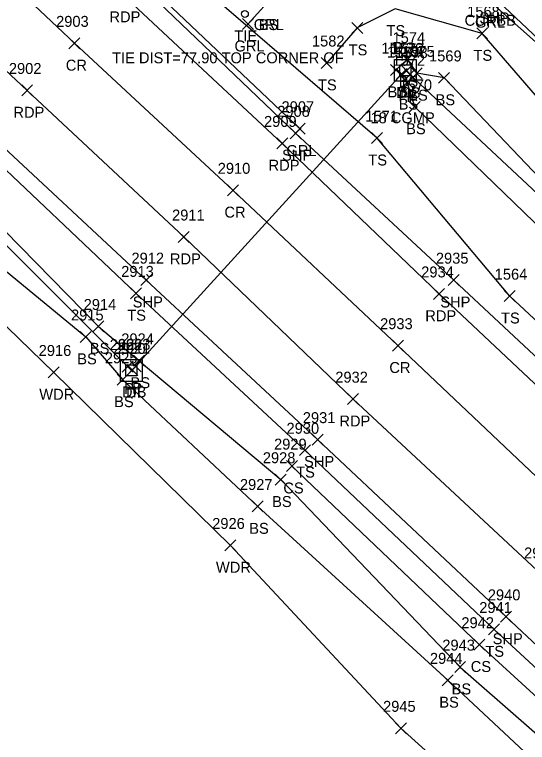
# Model space of a CAD drawing. Extents: x 1647574 to 1652703, y 212895 to 228670.
# Drawn here: x 1649146.1 to 1649239.7, y 226821.7 to 226954.6 of the extents above; entities that cross this region are included whole.
import ezdxf

# ---------------------------------------------------------------- set-up
doc = ezdxf.new("R2010")
doc.units = 0
for name, color, linetype in [('C_A', 7, 'Continuous'), ('C_C', 7, 'Continuous'), ('CBP', 7, 'Continuous'), ('D_A', 7, 'Continuous'), ('D_C', 7, 'Continuous'), ('D_I', 7, 'Continuous'), ('D_TIC', 7, 'Continuous'), ('DCP', 7, 'Continuous'), ('DS', 7, 'Continuous'), ('L_A', 7, 'Continuous'), ('L_I', 7, 'Continuous'), ('L_TIC', 7, 'Continuous'), ('LAWA', 7, 'Continuous'), ('LELB', 7, 'Continuous'), ('P_A', 7, 'Continuous'), ('P_I', 7, 'Continuous'), ('P_TIC', 7, 'Continuous'), ('PET', 7, 'Continuous'), ('PRC', 7, 'Continuous'), ('PSP', 7, 'Continuous'), ('R_A', 7, 'Continuous'), ('R_I', 7, 'Continuous'), ('R_TIC', 7, 'Continuous'), ('RGR', 7, 'Continuous')]:
    doc.layers.add(name, color=color, linetype=linetype)

msp = doc.modelspace()

# ---------------------------------------------------------------- linework, layer by layer
at = {"layer": 'CBP'}
msp.add_circle((1649188.13, 226954.68), 0.625, dxfattribs=at)
at = {"layer": 'D_TIC'}
for points in [[(1649215.77, 226942.73), (1649217.77, 226944.73)], [(1649217.77, 226942.73), (1649215.77, 226944.73)], [(1649216.65, 226943.32), (1649218.65, 226945.32)], [(1649218.65, 226943.32), (1649216.65, 226945.32)], [(1649217.25, 226942.62), (1649219.25, 226944.62)], [(1649219.25, 226942.62), (1649217.25, 226944.62)], [(1649165.73, 226889.31), (1649167.73, 226891.31)], [(1649167.73, 226889.31), (1649165.73, 226891.31)], [(1649166.59, 226888.68), (1649168.59, 226890.68)], [(1649168.59, 226888.68), (1649166.59, 226890.68)], [(1649167.19, 226889.36), (1649169.19, 226891.36)], [(1649169.19, 226889.36), (1649167.19, 226891.36)]]:
    msp.add_lwpolyline(points, dxfattribs=at)
at = {"layer": 'DCP'}
for points in [[(1649216.77, 226943.73), (1649168.19, 226890.36)], [(1649314.43, 226853.77), (1649218.25, 226943.62)], [(1649132.42, 226924.52), (1649166.73, 226890.31)]]:
    msp.add_lwpolyline(points, dxfattribs=at)
at = {"layer": 'DS'}
for p, q in [((1649215.43, 226946.39), (1649219.43, 226946.39)), ((1649215.43, 226942.39), (1649215.43, 226946.39)), ((1649219.43, 226946.39), (1649219.43, 226942.39)), ((1649216.43, 226943.39), (1649216.43, 226945.39)), ((1649216.43, 226945.39), (1649218.43, 226945.39)), ((1649218.43, 226945.39), (1649218.43, 226943.39)), ((1649218.43, 226943.39), (1649216.43, 226943.39)), ((1649217.44, 226944.39), (1649217.44, 226944.39)), ((1649217.44, 226944.39), (1649217.44, 226944.39)), ((1649219.43, 226942.39), (1649215.43, 226942.39)), ((1649165.41, 226891.6), (1649169.41, 226891.6)), ((1649165.41, 226887.6), (1649165.41, 226891.6)), ((1649169.41, 226891.6), (1649169.41, 226887.6)), ((1649166.41, 226888.6), (1649166.41, 226890.6)), ((1649166.41, 226890.6), (1649168.41, 226890.6)), ((1649168.41, 226890.6), (1649168.41, 226888.6)), ((1649167.42, 226889.6), (1649167.42, 226889.6)), ((1649167.42, 226889.6), (1649167.42, 226889.6)), ((1649169.41, 226887.6), (1649165.41, 226887.6)), ((1649168.41, 226888.6), (1649166.41, 226888.6))]:
    msp.add_line(p, q, dxfattribs=at)
at = {"layer": 'L_TIC'}
for points in [[(1649207.66, 226951.13), (1649209.66, 226953.13)], [(1649209.66, 226951.13), (1649207.66, 226953.13)], [(1649230.46, 226950.13), (1649232.46, 226952.13)], [(1649232.46, 226950.13), (1649230.46, 226952.13)], [(1649216.78, 226945.35), (1649218.78, 226947.35)], [(1649218.78, 226945.35), (1649216.78, 226947.35)], [(1649202.07, 226944.74), (1649204.07, 226946.74)], [(1649204.07, 226944.74), (1649202.07, 226946.74)], [(1649214.75, 226943.46), (1649216.75, 226945.46)], [(1649216.75, 226943.46), (1649214.75, 226945.46)], [(1649218.53, 226942.85), (1649220.53, 226944.85)], [(1649220.53, 226942.85), (1649218.53, 226944.85)], [(1649218.53, 226942.85), (1649220.53, 226944.85)], [(1649220.53, 226942.85), (1649218.53, 226944.85)], [(1649223.51, 226942.02), (1649225.51, 226944.02)], [(1649225.51, 226942.02), (1649223.51, 226944.02)], [(1649216.77, 226941.22), (1649218.77, 226943.22)], [(1649218.77, 226941.22), (1649216.77, 226943.22)], [(1649218.14, 226936.73), (1649220.14, 226938.73)], [(1649220.14, 226936.73), (1649218.14, 226938.73)], [(1649211.26, 226931.02), (1649213.26, 226933.02)], [(1649213.26, 226931.02), (1649211.26, 226933.02)], [(1649167.25, 226902.68), (1649169.25, 226904.68)], [(1649169.25, 226902.68), (1649167.25, 226904.68)], [(1649235.49, 226902.17), (1649237.49, 226904.17)], [(1649237.49, 226902.17), (1649235.49, 226904.17)], [(1649160.39, 226896.64), (1649162.39, 226898.64)], [(1649162.39, 226896.64), (1649160.39, 226898.64)], [(1649158.08, 226894.72), (1649160.08, 226896.72)], [(1649160.08, 226894.72), (1649158.08, 226896.72)], [(1649167.83, 226890.36), (1649169.83, 226892.36)], [(1649169.83, 226890.36), (1649167.83, 226892.36)], [(1649152.24, 226888.24), (1649154.24, 226890.24)], [(1649154.24, 226888.24), (1649152.24, 226890.24)], [(1649164.83, 226886.9), (1649166.83, 226888.9)], [(1649166.83, 226886.9), (1649164.83, 226888.9)], [(1649198.09, 226874.04), (1649200.09, 226876.04)], [(1649200.09, 226874.04), (1649198.09, 226876.04)], [(1649195.72, 226871.14), (1649197.72, 226873.14)], [(1649197.72, 226871.14), (1649195.72, 226873.14)], [(1649193.67, 226868.66), (1649195.67, 226870.66)], [(1649195.67, 226868.66), (1649193.67, 226870.66)], [(1649189.49, 226863.77), (1649191.49, 226865.77)], [(1649191.49, 226863.77), (1649189.49, 226865.77)], [(1649184.49, 226856.66), (1649186.49, 226858.66)], [(1649186.49, 226856.66), (1649184.49, 226858.66)], [(1649232.63, 226841.31), (1649234.63, 226843.31)], [(1649234.63, 226841.31), (1649232.63, 226843.31)], [(1649229.92, 226838.54), (1649231.92, 226840.54)], [(1649231.92, 226838.54), (1649229.92, 226840.54)], [(1649226.44, 226834.45), (1649228.44, 226836.45)], [(1649228.44, 226834.45), (1649226.44, 226836.45)], [(1649224.18, 226832.03), (1649226.18, 226834.03)], [(1649226.18, 226832.03), (1649224.18, 226834.03)], [(1649215.62, 226823.27), (1649217.62, 226825.27)], [(1649217.62, 226823.27), (1649215.62, 226825.27)]]:
    msp.add_lwpolyline(points, dxfattribs=at)
at = {"layer": 'LAWA'}
msp.add_lwpolyline([(1649041.49, 226996.32), (1649066.6, 226982.43), (1649084.99, 226955.58), (1649104.57, 226936.43), (1649153.24, 226889.24), (1649185.49, 226857.66), (1649216.62, 226824.27), (1649251.65, 226792.59), (1649287.92, 226760.12), (1649326.63, 226723.53), (1649357.26, 226688), (1649386.17, 226657.62), (1649416.75, 226628.4), (1649449.74, 226597.57), (1649490.53, 226561.68), (1649523.77, 226531.6), (1649564.01, 226501.21), (1649600.78, 226471.1)], dxfattribs=at)
at = {"layer": 'LELB'}
for points in [[(1649050.36, 227022.26), (1649054.5, 227019.16), (1649077.5, 226992.81), (1649097.35, 226965.43), (1649118.34, 226949.96), (1649138.54, 226931.84), (1649168.25, 226903.68), (1649199.09, 226875.04), (1649233.63, 226842.31), (1649267.99, 226810.62), (1649300.85, 226778.49), (1649342.51, 226739.65), (1649376.73, 226707.3), (1649405.44, 226679.92), (1649436.03, 226650.7), (1649471.83, 226617.33), (1649509.36, 226581.5), (1649541.59, 226550.78), (1649576.43, 226518.4), (1649614.41, 226482.98)], [(1649601.72, 226556.3), (1649565.56, 226590.44), (1649531.93, 226623.52), (1649496.55, 226657.42), (1649463.01, 226688.13), (1649429.09, 226720.61), (1649397.93, 226750.55), (1649357.87, 226787.13), (1649324.24, 226819.11), (1649290.45, 226852.03), (1649264.6, 226876.99), (1649236.49, 226903.17), (1649212.26, 226932.02), (1649172.55, 226966.26), (1649148.69, 226987.13), (1649125.3, 227007.74), (1649116.81, 227012.43), (1649123.68, 227011.79), (1649139.12, 227006.12), (1649163.74, 226998.25), (1649180.85, 226995.42), (1649185.97, 226996.02), (1649188.1, 226997.43)], [(1649593.12, 226613.01), (1649554.76, 226645.44), (1649523.05, 226677.15), (1649485.11, 226713.45), (1649453.02, 226743.38), (1649420.61, 226775.73), (1649384.19, 226809.44), (1649346.96, 226843.75), (1649308.84, 226878.4), (1649286.16, 226899.19), (1649254.43, 226924.59), (1649231.46, 226951.13), (1649215.58, 226955.64), (1649208.66, 226952.13), (1649203.07, 226945.74)], [(1649699.67, 226481.91), (1649679.45, 226501.99), (1649645.41, 226536.66), (1649612.61, 226568.57), (1649578.32, 226600.99), (1649543.98, 226632.95), (1649509.04, 226666.44), (1649473.07, 226698.81), (1649440.27, 226731.3), (1649435.72, 226737.04), (1649408.87, 226762.28), (1649371.65, 226797.42), (1649335.46, 226831.54), (1649323.17, 226842.84), (1649315.96, 226850.35), (1649312.9, 226852.88), (1649303.05, 226862.63), (1649272.9, 226885.04), (1649244.53, 226913.23), (1649219.14, 226937.73), (1649217.77, 226942.22), (1649215.75, 226944.46), (1649217.78, 226946.35), (1649219.53, 226943.85)], [(1649110.63, 226944.12), (1649132.81, 226926.76), (1649161.39, 226897.64), (1649168.83, 226891.36), (1649194.67, 226869.66), (1649227.44, 226835.45), (1649262.79, 226804.48), (1649294.65, 226771.03), (1649336.54, 226732.41), (1649369.74, 226699.93), (1649399.39, 226672.85), (1649429.85, 226642.79), (1649464.73, 226609.99), (1649502.63, 226572.81), (1649535.56, 226543.81), (1649570.19, 226510.51), (1649608.23, 226476.35)], [(1649699.67, 226481.91), (1649706.82, 226489.3), (1649683.4, 226506.92), (1649648.98, 226540.18), (1649615.46, 226571.75), (1649582.54, 226604.31), (1649545.88, 226635.11), (1649514.99, 226670.75), (1649476.91, 226703.47), (1649443.87, 226735.13), (1649437.39, 226738.45), (1649410.25, 226763.49), (1649372.93, 226798.59), (1649336.35, 226832.76), (1649324.5, 226844.21), (1649317.41, 226851.47), (1649314.57, 226854.84), (1649305.82, 226864.42), (1649279.73, 226892.76), (1649248.17, 226918.18), (1649224.51, 226943.02), (1649219.53, 226943.85)], [(1649107.55, 226940.79), (1649127.63, 226921.57), (1649159.08, 226895.72), (1649165.83, 226887.9), (1649190.49, 226864.77), (1649225.18, 226833.03), (1649259.69, 226800.81), (1649292.76, 226768.97), (1649332.89, 226728.92), (1649366.72, 226696.88), (1649396.96, 226668.92), (1649427.38, 226640.01), (1649462.61, 226607.88), (1649501.23, 226571.04), (1649533.66, 226541.41), (1649568.55, 226508.33), (1649606.13, 226474.18), (1649635.06, 226446.4), (1649657.11, 226422.45)], [(1649196.72, 226872.14), (1649230.92, 226839.54), (1649265.68, 226807.77), (1649297.02, 226774.6), (1649340.28, 226737.1), (1649373.28, 226703.68), (1649402.3, 226677.38), (1649432.52, 226646.6), (1649468.42, 226614.12), (1649504.95, 226574.73), (1649537.46, 226545.9), (1649572.06, 226513.32), (1649610.08, 226478.23)]]:
    msp.add_lwpolyline(points, dxfattribs=at)
at = {"layer": 'P_TIC'}
for points in [[(1649156.01, 226948.33), (1649158.01, 226950.33)], [(1649158.01, 226948.33), (1649156.01, 226950.33)], [(1649147.39, 226939.73), (1649149.39, 226941.73)], [(1649149.39, 226939.73), (1649147.39, 226941.73)], [(1649196.39, 226931.91), (1649198.39, 226933.91)], [(1649198.39, 226931.91), (1649196.39, 226933.91)], [(1649193.97, 226930.06), (1649195.97, 226932.06)], [(1649195.97, 226930.06), (1649193.97, 226932.06)], [(1649184.96, 226921.5), (1649186.96, 226923.5)], [(1649186.96, 226921.5), (1649184.96, 226923.5)], [(1649175.97, 226912.97), (1649177.97, 226914.97)], [(1649177.97, 226912.97), (1649175.97, 226914.97)], [(1649169.13, 226905.1), (1649171.13, 226907.1)], [(1649171.13, 226905.1), (1649169.13, 226907.1)], [(1649225.27, 226905.09), (1649227.27, 226907.09)], [(1649227.27, 226905.09), (1649225.27, 226907.09)], [(1649222.59, 226902.58), (1649224.59, 226904.58)], [(1649224.59, 226902.58), (1649222.59, 226904.58)], [(1649215.08, 226893.13), (1649217.08, 226895.13)], [(1649217.08, 226893.13), (1649215.08, 226895.13)], [(1649206.9, 226883.37), (1649208.9, 226885.37)], [(1649208.9, 226883.37), (1649206.9, 226885.37)], [(1649200.41, 226875.98), (1649202.41, 226877.98)], [(1649202.41, 226875.98), (1649200.41, 226877.98)], [(1649234.83, 226843.62), (1649236.83, 226845.62)], [(1649236.83, 226843.62), (1649234.83, 226845.62)]]:
    msp.add_lwpolyline(points, dxfattribs=at)
at = {"layer": 'PET'}
for points in [[(1649049.09, 227034.42), (1649086.52, 226998.96), (1649109.21, 226977.52), (1649148.39, 226940.73), (1649176.97, 226913.97), (1649207.9, 226884.37), (1649242.38, 226852.27), (1649276.93, 226819.76), (1649310.57, 226787.99), (1649351.53, 226749.66), (1649386.03, 226717.08), (1649415.53, 226689.26), (1649446.48, 226660.42), (1649481.94, 226626.92), (1649519.05, 226591.95), (1649551.76, 226560.83), (1649585.69, 226528.77), (1649624.3, 226492.34)], [(1649093.95, 227025.5), (1649126.98, 226994.68), (1649165.92, 226958.16), (1649194.97, 226931.06), (1649223.59, 226903.58), (1649259.38, 226869.94), (1649293.46, 226837.81), (1649328.56, 226805.25), (1649367.41, 226768.36), (1649403.39, 226734.5), (1649427.73, 226711.63), (1649463.63, 226677.53), (1649497.38, 226645.66), (1649535.82, 226609.26), (1649568.76, 226578.15), (1649602.84, 226545.72)]]:
    msp.add_lwpolyline(points, dxfattribs=at)
at = {"layer": 'PRC'}
msp.add_lwpolyline([(1649071, 227030.27), (1649097.26, 227005.13), (1649118.09, 226986.08), (1649157.01, 226949.33), (1649185.96, 226922.5), (1649216.08, 226894.13), (1649250.58, 226861.49), (1649285.59, 226828.84), (1649319.08, 226797.05), (1649359.19, 226759.47), (1649394.66, 226725.95), (1649419.6, 226702.04), (1649454.56, 226669.33), (1649489.14, 226637.08), (1649527.32, 226600.87), (1649559.91, 226569.96), (1649593.92, 226537.25)], dxfattribs=at)
at = {"layer": 'PSP'}
for points in [[(1649099.96, 227024.6), (1649093.95, 227025.5), (1649071, 227030.27), (1649049.09, 227034.42), (1649045.28, 227034.88), (1649054.51, 227026.18), (1649082.27, 226995.84), (1649103.4, 226971.49), (1649121.95, 226952.01), (1649133.13, 226940.72), (1649140.44, 226933.69), (1649170.13, 226906.1), (1649201.41, 226876.98), (1649235.83, 226844.62), (1649270.02, 226812.62), (1649303.26, 226781.03), (1649344.74, 226742.14), (1649379.28, 226709.76), (1649407.94, 226682.37), (1649438.57, 226653.08), (1649474.06, 226619.55), (1649511.81, 226584.21), (1649544.44, 226553.59), (1649578.75, 226520.79)], [(1649099.96, 227024.6), (1649112.12, 227013.19), (1649129.86, 226996.81), (1649168.15, 226960.9), (1649197.39, 226932.91), (1649226.27, 226906.09), (1649262.03, 226872.71), (1649296.02, 226840.81), (1649331.67, 226807.62), (1649370.43, 226771.63), (1649405.77, 226737.7), (1649429.96, 226714.79), (1649466.37, 226680.16), (1649499.94, 226648.68), (1649538.12, 226612.04), (1649571.18, 226581.28), (1649605.62, 226548.46)], [(1649595.64, 226615.02), (1649558.33, 226650.15), (1649527.09, 226680.38), (1649488.24, 226717.06), (1649456.66, 226746.86), (1649422.68, 226779.06), (1649387.28, 226812.32), (1649351.05, 226846.64), (1649313.21, 226882.31), (1649279.73, 226913.94), (1649251.2, 226941.22), (1649233.38, 226957.97), (1649213.56, 226976.76), (1649200.33, 226989.45), (1649199.76, 226990.72), (1649190.94, 226999.11)]]:
    msp.add_lwpolyline(points, dxfattribs=at)
at = {"layer": 'R_TIC'}
for points in [[(1649187.7, 226951.84), (1649189.7, 226953.84)], [(1649189.7, 226951.84), (1649187.7, 226953.84)], [(1649197.17, 226932.74), (1649199.17, 226934.74)], [(1649199.17, 226932.74), (1649197.17, 226934.74)]]:
    msp.add_lwpolyline(points, dxfattribs=at)
at = {"layer": 'RGR'}
for points in [[(1649113.64, 227012.86), (1649130.4, 226998.11), (1649168.97, 226961.45), (1649198.17, 226933.74)], [(1649553.69, 226650.38), (1649526.88, 226680.04), (1649487.89, 226716.68), (1649456.34, 226746.59), (1649422.28, 226778.82), (1649386.82, 226812.08), (1649350.56, 226846.46), (1649313.1, 226882.03), (1649279.45, 226913.72), (1649250.85, 226941.01), (1649232.6, 226957.18), (1649212.72, 226976.44), (1649200.04, 226988.83)], [(1649188.7, 226952.84), (1649192.21, 226956.74), (1649207.4, 226972.4)]]:
    msp.add_lwpolyline(points, dxfattribs=at)

# ---------------------------------------------------------------- texts
at = {"layer": 'C_A'}
msp.add_text('TIE', height=2, dxfattribs=at).set_placement((1649186.21, 226949.68))
at = {"layer": 'C_C'}
msp.add_text('TIE DIST=77.90 TOP CORNER OF', height=2, dxfattribs=at).set_placement((1649163.89, 226945.68))
at = {"layer": 'D_A'}
for s, p in [('DIB', (1649215.76, 226939.32)), ('P', (1649216.15, 226938.73)), ('DI', (1649216.49, 226939.39)), ('P', (1649217.63, 226938.62)), ('DIB', (1649165.7, 226884.68)), ('P', (1649166.11, 226885.31)), ('DI', (1649166.47, 226884.6)), ('P', (1649167.57, 226885.36))]:
    msp.add_text(s, height=2, dxfattribs=at).set_placement(p)
at = {"layer": 'D_C'}
msp.add_text('18 CGMP', height=2, dxfattribs=at).set_placement((1649211.06, 226934.73))
at = {"layer": 'D_I'}
for s, p in [('1579', (1649214.07, 226946.73)), ('1576', (1649214.69, 226947.39)), ('1577', (1649214.96, 226947.32)), ('1578', (1649215.56, 226946.62)), ('2922', (1649163.47, 226893.31)), ('2920', (1649164.07, 226892.6)), ('2921', (1649164.9, 226892.68)), ('2923', (1649164.94, 226893.36))]:
    msp.add_text(s, height=2, dxfattribs=at).set_placement(p)
at = {"layer": 'L_A'}
for s, p in [('BS', (1649190.65, 226951.74)), ('TS', (1649213.99, 226950.64)), ('TS', (1649207.07, 226947.13)), ('TS', (1649229.87, 226946.13)), ('BS', (1649216.22, 226941.35)), ('TS', (1649201.48, 226940.74)), ('BS', (1649214.19, 226939.46)), ('BS', (1649217.97, 226938.85)), ('BS', (1649217.97, 226938.85)), ('BS', (1649222.95, 226938.02)), ('BS', (1649216.21, 226937.22)), ('BS', (1649217.58, 226932.73)), ('TS', (1649210.67, 226927.02)), ('TS', (1649166.66, 226898.68)), ('TS', (1649234.9, 226898.17)), ('BS', (1649159.83, 226892.64)), ('BS', (1649157.53, 226890.72)), ('BS', (1649167.27, 226886.36)), ('WDR', (1649150.6, 226884.24)), ('BS', (1649164.27, 226882.9)), ('TS', (1649197.5, 226870.04)), ('CS', (1649195.16, 226867.14)), ('BS', (1649193.11, 226864.66)), ('BS', (1649188.93, 226859.77)), ('WDR', (1649182.85, 226852.66)), ('TS', (1649232.04, 226837.31)), ('CS', (1649229.37, 226834.54)), ('BS', (1649225.88, 226830.45)), ('BS', (1649223.63, 226828.03))]:
    msp.add_text(s, height=2, dxfattribs=at).set_placement(p)
at = {"layer": 'L_I'}
for s, p in [('1568', (1649228.72, 226954.13)), ('1574', (1649215.09, 226949.35)), ('1582', (1649200.38, 226948.74)), ('1573', (1649213.06, 226947.46)), ('1575', (1649216.84, 226946.85)), ('1575', (1649216.84, 226946.85)), ('1569', (1649221.76, 226946.02)), ('1572', (1649215.07, 226945.22)), ('1570', (1649216.36, 226940.73)), ('1571', (1649210.13, 226935.02)), ('2913', (1649165.56, 226906.68)), ('1564', (1649233.75, 226906.17)), ('2914', (1649158.7, 226900.64)), ('2915', (1649156.39, 226898.72)), ('2924', (1649165.57, 226894.36)), ('2916', (1649150.49, 226892.24)), ('2925', (1649162.57, 226890.9)), ('2930', (1649195.74, 226878.04)), ('2929', (1649193.46, 226875.14)), ('2928', (1649191.41, 226872.66)), ('2927', (1649187.23, 226867.77)), ('2926', (1649182.17, 226860.66)), ('2941', (1649230.93, 226845.31)), ('2942', (1649227.66, 226842.54)), ('2943', (1649224.18, 226838.45)), ('2944', (1649221.92, 226836.03)), ('2945', (1649213.36, 226827.27))]:
    msp.add_text(s, height=2, dxfattribs=at).set_placement(p)
at = {"layer": 'P_A'}
for s, p in [('RDP', (1649163.41, 226953.16)), ('SHP', (1649230.92, 226952.97)), ('CR', (1649155.44, 226944.33)), ('RDP', (1649145.88, 226935.73)), ('SHP', (1649194.93, 226927.91)), ('RDP', (1649192.46, 226926.06)), ('CR', (1649184.4, 226917.5)), ('RDP', (1649174.45, 226908.97)), ('SHP', (1649167.66, 226901.1)), ('SHP', (1649223.81, 226901.09)), ('RDP', (1649221.07, 226898.58)), ('CR', (1649214.51, 226889.13)), ('RDP', (1649205.39, 226879.37)), ('SHP', (1649198.94, 226871.98)), ('SHP', (1649233.37, 226839.62))]:
    msp.add_text(s, height=2, dxfattribs=at).set_placement(p)
at = {"layer": 'P_I'}
for s, p in [('2903', (1649153.67, 226952.33)), ('2902', (1649145.05, 226943.73)), ('2908', (1649194.05, 226935.91)), ('2909', (1649191.63, 226934.06)), ('2910', (1649183.18, 226925.5)), ('2911', (1649174.84, 226916.97)), ('2912', (1649167.43, 226909.1)), ('2935', (1649223.01, 226909.09)), ('2934', (1649220.33, 226906.58)), ('2933', (1649212.82, 226897.13)), ('2932', (1649204.64, 226887.37)), ('2931', (1649198.71, 226879.98)), ('2939', (1649239.11, 226855.27)), ('2940', (1649232.49, 226847.62))]:
    msp.add_text(s, height=2, dxfattribs=at).set_placement(p)
at = {"layer": 'R_A'}
for s, p in [('CURBB', (1649228.25, 226952.53)), ('GRL', (1649230.15, 226952.18)), ('GRL', (1649189.75, 226951.74)), ('GRL', (1649186.24, 226947.84)), ('GRL', (1649195.72, 226928.74))]:
    msp.add_text(s, height=2, dxfattribs=at).set_placement(p)
at = {"layer": 'R_I'}
msp.add_text('2907', height=2, dxfattribs=at).set_placement((1649194.83, 226936.74))

doc.saveas('drawing.dxf')
